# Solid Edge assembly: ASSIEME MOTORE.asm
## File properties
Subject: ASSIEME MOTORE
Author: f_grande
Template: Normal.asm
Last saved by: f_grande
Revision: 14
Application: Solid Edge
Tipo di contenuto documento: 1
Document Number: KR0300
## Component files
SUPPORTO CUSC 7201_r1.par
SUPPORTO MOTORE_2.par
Connettore_ele.par
TCEI M4x25.par
Coupling_6.35mm x 8.00mm.asm
SANYO_NEMA23_103_H7126.par
Squadretta.par
Supporto_Cablaggio.psm
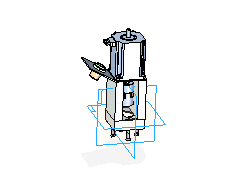
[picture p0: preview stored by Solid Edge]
